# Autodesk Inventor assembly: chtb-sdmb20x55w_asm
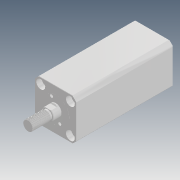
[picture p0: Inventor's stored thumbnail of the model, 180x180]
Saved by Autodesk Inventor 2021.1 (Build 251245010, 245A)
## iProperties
Company: Microsoft
Created: 2018-05
Part Number: chtb-sdmb20x55w_asm
Description: STEP AP214
Document SubType Name: Assembly
Designer: user
Title: chtb-sdmb20x55w_asm.STEP
Author: Windows
Revision Number: ÈÎºÎ
Sending System: SolidWorks 2015
Preprocessor: SwSTEP 2.0
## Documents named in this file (4)
- D:\Vault_2016\Projekty\Clamptek\Hydraulic\CHTB\CHTB-20\Inventor\CHTB-SDMB20x55W\chtb-sdmb20x55w_asm.iam
- D:\Vault_2016\Projekty\Clamptek\Hydraulic\CHTB\CHTB-20\Inventor\CHTB-SDMB20x55W\CHTB-SDMB20X55NBT.ipt
- D:\Vault_2016\Projekty\Clamptek\Hydraulic\CHTB\CHTB-20\Inventor\CHTB-SDMB20x55W\CHTB-SDMB20X55WHSG.ipt
- D:\Vault_2016\Projekty\Clamptek\Hydraulic\CHTB\CHTB-20\Inventor\CHTB-SDMB20x55W\QG_3.ipt
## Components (3 placed, 3 different names)
1. CHTB-SDMB20X55NBT_1
2. CHTB-SDMB20X55WHSG_2
3. QG_3_3
